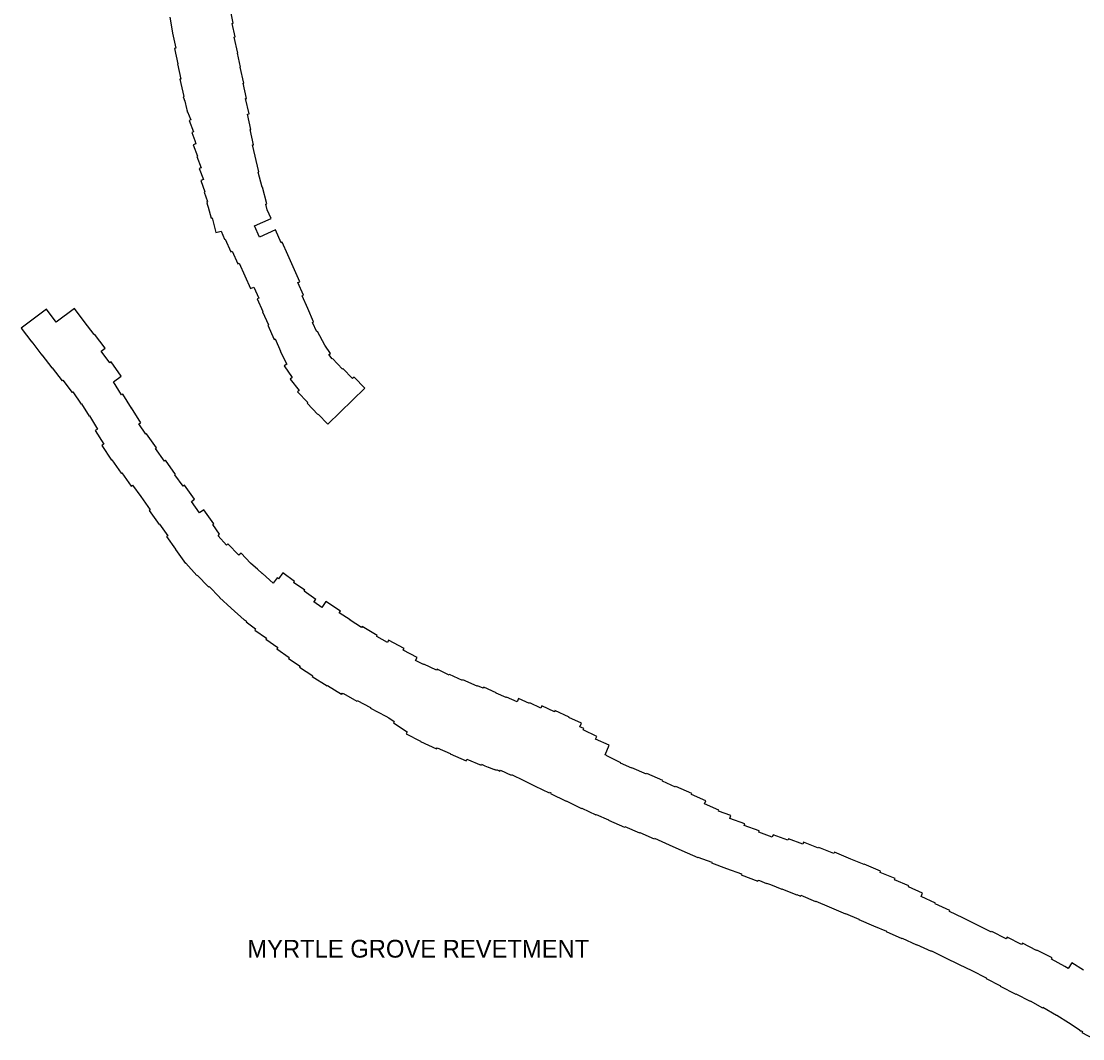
# Model space of a CAD drawing. Extents: x 2650582 to 3923188, y 277893 to 989177.
# Drawn here: x 3716952 to 3726510, y 414395 to 423558 of the extents above; entities that cross this region are included whole.
import ezdxf

# ---------------------------------------------------------------- set-up
doc = ezdxf.new("R2010")
doc.units = 0
doc.layers.add('Level 3', color=7, linetype='Continuous')

msp = doc.modelspace()

# ---------------------------------------------------------------- linework, layer by layer
at = {"layer": 'Level 3'}
for points in [[(3719166.7, 421859.8), (3719155.1, 421910.8), (3719164.7, 421913.3), (3719123.1, 422064.5), (3719120.7, 422063.7), (3719085.6, 422200.3), (3719090.5, 422202), (3719034.3, 422444.9), (3719042.4, 422446.5), (3719012.2, 422583.1), (3719020.4, 422584.8), (3718990.6, 422720.7), (3719003.7, 422723.5), (3718972.4, 422861.6), (3718979.5, 422863.1), (3718948.8, 423001.2), (3718954.9, 423002.2), (3718923.5, 423144.7), (3718926.1, 423145.1), (3718897.7, 423271), (3718901.1, 423271.8), (3718867.9, 423416), (3718878.5, 423419.1), (3718852.2, 423538.8), (3718860.8, 423540.4), (3718830.8, 423694.4)], [(3718289.9, 423594), (3718315.3, 423453), (3718313, 423452.3), (3718342.5, 423315.3), (3718333.1, 423313.2), (3718361.9, 423175.3), (3718359, 423174.3), (3718389, 423038.2), (3718380.7, 423036), (3718415.8, 422879.8), (3718410.4, 422877.7), (3718425.1, 422839.4), (3718440.4, 422772.5), (3718438.7, 422771.8), (3718443.3, 422759.6), (3718447.6, 422740.8), (3718450.3, 422741.5), (3718477.7, 422670.1), (3718463.2, 422664.5), (3718502.3, 422562.7), (3718488, 422557.3), (3718516.2, 422483.9), (3718523.1, 422454), (3718499.2, 422444.8), (3718538.2, 422343), (3718531.9, 422340.6), (3718570.9, 422238.8), (3718555.3, 422232.8), (3718593.7, 422132.8), (3718567.6, 422123.3), (3718604.9, 422020.9), (3718597.8, 422018.3), (3718627.7, 421935.9), (3718621.8, 421934.2), (3718625.5, 421920.1), (3718623.6, 421919.5), (3718635.3, 421883.5), (3718661.6, 421784.6), (3718670.6, 421786.9), (3718703.2, 421655.2), (3718751.1, 421667.2)], [(3719712.3, 419930.3), (3720047.1, 420253.5), (3719949.8, 420354.2), (3719935.2, 420340), (3719848.3, 420429.9), (3719844.9, 420426.6), (3719753.2, 420521.5), (3719751.3, 420519.8), (3719721.6, 420556.4), (3719735.3, 420565.6), (3719684.8, 420640.4), (3719685.9, 420641.1), (3719620.2, 420764.7), (3719612.4, 420760.6), (3719574, 420846.9), (3719584.3, 420851.5), (3719531.6, 420970.3), (3719533, 420970.9), (3719482.2, 421085.2), (3719493.4, 421090.2), (3719442.8, 421204.4), (3719460.2, 421212.3), (3719353.6, 421454.8), (3719351.3, 421453.6), (3719300.7, 421568), (3719292.7, 421564.4), (3719241.5, 421678.7), (3719096.7, 421614.1), (3719052.1, 421714.7), (3719201.7, 421781.3), (3719166.7, 421859.8)], [(3718751.1, 421667.2), (3718783.3, 421595), (3718787.7, 421597), (3718838.6, 421482.8), (3718851.2, 421488.5), (3718902.3, 421374.3), (3718914.5, 421379.9), (3719015.9, 421151.3), (3719045.7, 421164.6), (3719090.4, 421064.2), (3719076.5, 421058), (3719127.3, 420943.8), (3719124.3, 420942.4), (3719177.2, 420823.7), (3719171.1, 420821.1), (3719227.9, 420693), (3719238.1, 420697.7), (3719286.8, 420587.9), (3719283.3, 420586), (3719344.3, 420470.8), (3719320, 420454.4), (3719391, 420349.2), (3719372.9, 420334.8), (3719455, 420233.5), (3719440.6, 420219.8), (3719532.3, 420124.7), (3719525.7, 420118.5), (3719622.9, 420017.8), (3719625.3, 420020.1), (3719712.3, 419930.3)], [(3718676.7, 419025.3), (3718685.5, 419031.6), (3718596, 419157.4), (3718558.3, 419130.6), (3718484.1, 419235), (3718511.3, 419254.3), (3718421.6, 419380.2), (3718408.6, 419371), (3718335.7, 419473.4), (3718341.8, 419477.7), (3718251.4, 419604.6), (3718241.9, 419597.9), (3718162.2, 419709.9), (3718169.9, 419715.4), (3718079.5, 419842.3), (3718074.1, 419838.6), (3718011.7, 419932.7), (3718027.2, 419942.3), (3717944.4, 420076), (3717943.7, 420075.5), (3717865.8, 420201.4), (3717855, 420194.7), (3717782.2, 420312.3), (3717852.5, 420361.1), (3717763, 420490.1), (3717751, 420481.8), (3717670.5, 420587.7), (3717706.4, 420615), (3717611.5, 420739.8), (3717609.3, 420738.1), (3717519.7, 420855.9), (3717519.2, 420855.5), (3717430.4, 420972.3), (3717266, 420847.3), (3717178.1, 420964.1), (3716951.8, 420793.7), (3717046, 420668.6), (3717048.5, 420670.4), (3717137.9, 420552.8), (3717138.4, 420553.2), (3717227.3, 420436.4), (3717229.5, 420438.1), (3717319, 420320.3), (3717326.7, 420326.1), (3717410.5, 420215.8), (3717415.8, 420219.9), (3717491.6, 420110.7), (3717494.4, 420112.6), (3717562.6, 420002.3), (3717565.2, 420003.9), (3717638, 419886.3), (3717618.4, 419874.1), (3717695.2, 419750.2), (3717677.2, 419738.3), (3717764.2, 419607.2), (3717767.1, 419609.2), (3717852.5, 419489.4), (3717856.8, 419492.4), (3717942.3, 419372.2), (3717954.6, 419380.8), (3718028.1, 419277.5), (3718028.1, 419277.5), (3718112.2, 419159.7), (3718103.2, 419153.4), (3718192.9, 419027.5), (3718196.4, 419029.9), (3718270.6, 418925.7), (3718260.1, 418918.2), (3718342, 418803.2), (3718341.1, 418802.5)], [(3719307.9, 418591.2), (3719266.9, 418536.7), (3719255.8, 418545.5), (3719219.5, 418499.5), (3719124.1, 418585.5), (3719122.6, 418583.9), (3719078.9, 418623.3), (3719062.1, 418638.3), (3719016.4, 418679.8), (3718930.7, 418768.7), (3718910.3, 418748.9), (3718811.9, 418851.1), (3718800.2, 418839.9), (3718726, 418924.6), (3718737, 418940.8), (3718676.7, 419025.3)], [(3718341.1, 418802.5), (3718430.7, 418676.7), (3718433.8, 418678.9), (3718532.4, 418566.3), (3718536.9, 418570.1), (3718638.5, 418464.6), (3718642.7, 418468.7), (3718737, 418370.8), (3718736.7, 418370.5), (3718843.2, 418274.3), (3718841.9, 418272.8), (3718959.6, 418166.6), (3718962.2, 418169.4), (3718979.9, 418155.5)], [(3720577.6, 417770.3), (3720574.8, 417764.7), (3720502.8, 417802.8), (3720516, 417827.6), (3720391.1, 417893.9), (3720400, 417910.7), (3720260.2, 417984.9), (3720248.5, 417963), (3720152.2, 418017.8), (3720156.9, 418025.5), (3720020.8, 418108.2), (3720015.5, 418099.4), (3719912.5, 418164.4), (3719914.1, 418166.9), (3719814.5, 418229.8), (3719826, 418247.5), (3719693.1, 418334), (3719658.1, 418280.3), (3719587.8, 418330.2), (3719603.5, 418352.5), (3719498.5, 418426.8), (3719504, 418434.6), (3719404.7, 418504.9), (3719411.1, 418513.5), (3719307.9, 418591.2)], [(3718979.9, 418155.5), (3718976.6, 418151.1), (3719062.5, 418086.4), (3719055.4, 418076.3), (3719160.4, 418001.9), (3719154.9, 417994.1), (3719263.1, 417917.6), (3719254.6, 417905.6), (3719363.8, 417828.3), (3719358.4, 417820.2), (3719464, 417751.4), (3719457.1, 417740.4), (3719576.4, 417665.1), (3719571.4, 417657.3), (3719705.9, 417572.4), (3719708.7, 417576.9), (3719837, 417498.9), (3719841.7, 417506.6), (3719852, 417500.3), (3719854.3, 417504), (3719972.7, 417436.5), (3719976.4, 417443), (3720098, 417378.4), (3720095.7, 417374), (3720235.6, 417299.7), (3720235.6, 417299.8), (3720260.6, 417286.6)], [(3721415.9, 417430.2), (3721319.8, 417471.7), (3721318.6, 417468.8), (3721228.2, 417507.8), (3721229.3, 417510), (3721116.9, 417562.5), (3721111.8, 417551.5), (3721058.6, 417574.5), (3721057.2, 417571.5), (3720928.3, 417627.7), (3720925.5, 417621.3), (3720808.5, 417675.8), (3720805.3, 417668.9), (3720695.8, 417724), (3720690.5, 417713.4), (3720577.6, 417770.3)], [(3721982, 417205.1), (3721996.4, 417236.1), (3721883.1, 417288.9), (3721884.4, 417291.7), (3721757.5, 417350.8), (3721752.7, 417340.6), (3721639.6, 417393.5), (3721630.3, 417374), (3721531.7, 417420), (3721528.7, 417413.8), (3721429.8, 417459.9), (3721415.9, 417430.2)], [(3720260.6, 417286.6), (3720310.4, 417252.9), (3720302.8, 417241.4), (3720427.7, 417158.9), (3720418.6, 417141.7), (3720546.8, 417074.2), (3720545.5, 417071.3), (3720691.3, 417005.5), (3720696, 417016), (3720813.9, 416965.3), (3720812.8, 416962.6), (3720959, 416899.7), (3720964.8, 416913), (3721092.2, 416858.2), (3721096.3, 416867.7), (3721127.5, 416854.2), (3721157.5, 416840.2), (3721157.9, 416841.1), (3721208.7, 416819.2), (3721209.8, 416821.9), (3721228.5, 416813.9), (3721230.7, 416819), (3721261.3, 416804.8), (3721265.9, 416814.5), (3721363.6, 416767.8), (3721366.7, 416774.4), (3721476.7, 416721.8), (3721476, 416720.2), (3721578.6, 416671.2), (3721578, 416669.9), (3721704.8, 416610.7), (3721706.9, 416615.1), (3721719, 416609.5), (3721716.4, 416603.9), (3721857.9, 416536.4), (3721858.1, 416536.9)], [(3722209.3, 416953.5), (3722247.1, 417038), (3722123.6, 417093.3), (3722135.5, 417118), (3722012.1, 417177), (3722017.5, 417188.7), (3721982, 417205.1)], [(3726234.7, 415124.2), (3726096.4, 415194.8), (3726094.8, 415191.4), (3725966, 415257.1), (3725959.2, 415243.5), (3725828.3, 415310.3), (3725820.8, 415295.5), (3725691.2, 415361.6), (3725688, 415355.4), (3725568.2, 415414), (3725569.5, 415416.8), (3725430.7, 415484.7), (3725430.2, 415483.6), (3725309.7, 415542.5), (3725313.9, 415551.5), (3725182.4, 415611.6), (3725185.3, 415617.8), (3725055.1, 415677.3), (3725068.1, 415705.6), (3724940.3, 415764), (3724944.5, 415773.8), (3724815.4, 415827.4), (3724819.9, 415838.2), (3724685.4, 415894), (3724690.2, 415905), (3724542.3, 415966.4), (3724541.4, 415964.2), (3724421.9, 416013.8), (3724422.1, 416014.2), (3724274.4, 416075.6), (3724269.1, 416063), (3724133.7, 416119.1), (3724130.5, 416111.6), (3723996.7, 416167.2), (3723989, 416149), (3723859, 416196.4), (3723854.8, 416184.9), (3723722.9, 416233), (3723714.4, 416210), (3723591.8, 416254.6), (3723596.5, 416267.7), (3723461, 416317.1), (3723465.8, 416330.2), (3723330.7, 416379.4), (3723340.4, 416406), (3723230.6, 416446.1), (3723233.8, 416453.2), (3723104.4, 416510.9), (3723116.5, 416537.9), (3722987.1, 416595.6), (3722990.4, 416603), (3722846.5, 416667.2), (3722844, 416661.5), (3722726.4, 416714), (3722729.1, 416720.1), (3722585.4, 416784.2), (3722582.3, 416777.2), (3722450.2, 416836.2), (3722448.8, 416833), (3722348.4, 416877.8), (3722350.1, 416881.3), (3722223.3, 416941.9), (3722225.2, 416945.9), (3722209.3, 416953.5)], [(3721858.1, 416536.9), (3721997.8, 416470.1), (3721998.7, 416472), (3722125.5, 416411.4), (3722127.8, 416416.3), (3722240.5, 416366), (3722240.2, 416365.4), (3722383.9, 416301.3), (3722387, 416308.3), (3722519.1, 416249.3), (3722521.1, 416253.7), (3722650.5, 416196), (3722653, 416201.6), (3722785.1, 416142.7), (3722785.3, 416143.2), (3722899.5, 416092.2), (3722899.1, 416091.3), (3723043.6, 416026.9), (3723044.9, 416029.9), (3723169.4, 415984.4), (3723167.2, 415978.5), (3723302.3, 415929.2), (3723302.1, 415928.6), (3723437.2, 415879.3), (3723434.2, 415871.1), (3723585, 415816.1), (3723587.9, 415824), (3723600.6, 415819.4), (3723662.7, 415794), (3723663.7, 415796.4), (3723697.8, 415784), (3723799.1, 415742.5), (3723800.5, 415746.2), (3723807.5, 415743.6), (3723935.8, 415691.1), (3723936.7, 415693.2), (3723967.9, 415680.2), (3723971, 415687.7), (3724104.9, 415632.1), (3724105.4, 415633.3), (3724226.5, 415583), (3724226.3, 415582.6), (3724374, 415521.2), (3724374.9, 415523.4), (3724494.8, 415473.7), (3724493, 415469.1), (3724627.1, 415413.4), (3724626.2, 415411.3), (3724741.8, 415363.3), (3724740.9, 415361.4), (3724881.6, 415297.2), (3724883, 415300.2), (3725013.1, 415240.8), (3725014.1, 415243), (3725145.6, 415183), (3725146.9, 415185.9), (3725268.4, 415126.5), (3725268.9, 415127.5), (3725397.5, 415064.7)], [(3726411.6, 415078.7), (3726379.8, 415028.1), (3726349.2, 415045.9), (3726348.6, 415044.9), (3726229.4, 415113.8), (3726234.7, 415124.2)], [(3725397.5, 415064.7), (3725398, 415065.8), (3725511.8, 415010.2), (3725511.7, 415009.9), (3725641.1, 414943.8), (3725638.7, 414939), (3725769.5, 414872.2), (3725767.5, 414868.3), (3725905.9, 414797.7), (3725907.6, 414801), (3726036.2, 414735.3), (3726037.1, 414736.9), (3726147, 414673.4), (3726150.5, 414679.4), (3726274.9, 414607.4), (3726275.7, 414608.8), (3726381.7, 414542.5), (3726380.5, 414540.7), (3726469.3, 414485.1), (3726494.8, 414465.2), (3726496.9, 414467.8), (3726506.3, 414461.9), (3726501, 414451.6), (3726608.6, 414395.5)], [(3726516.1, 415012.9), (3726411.6, 415078.7)]]:
    msp.add_lwpolyline(points, dxfattribs=at)

# ---------------------------------------------------------------- texts
msp.add_text('MYRTLE GROVE REVETMENT', height=159.999, dxfattribs=at).set_placement((3718987.3, 415126.4))

doc.saveas('drawing.dxf')
